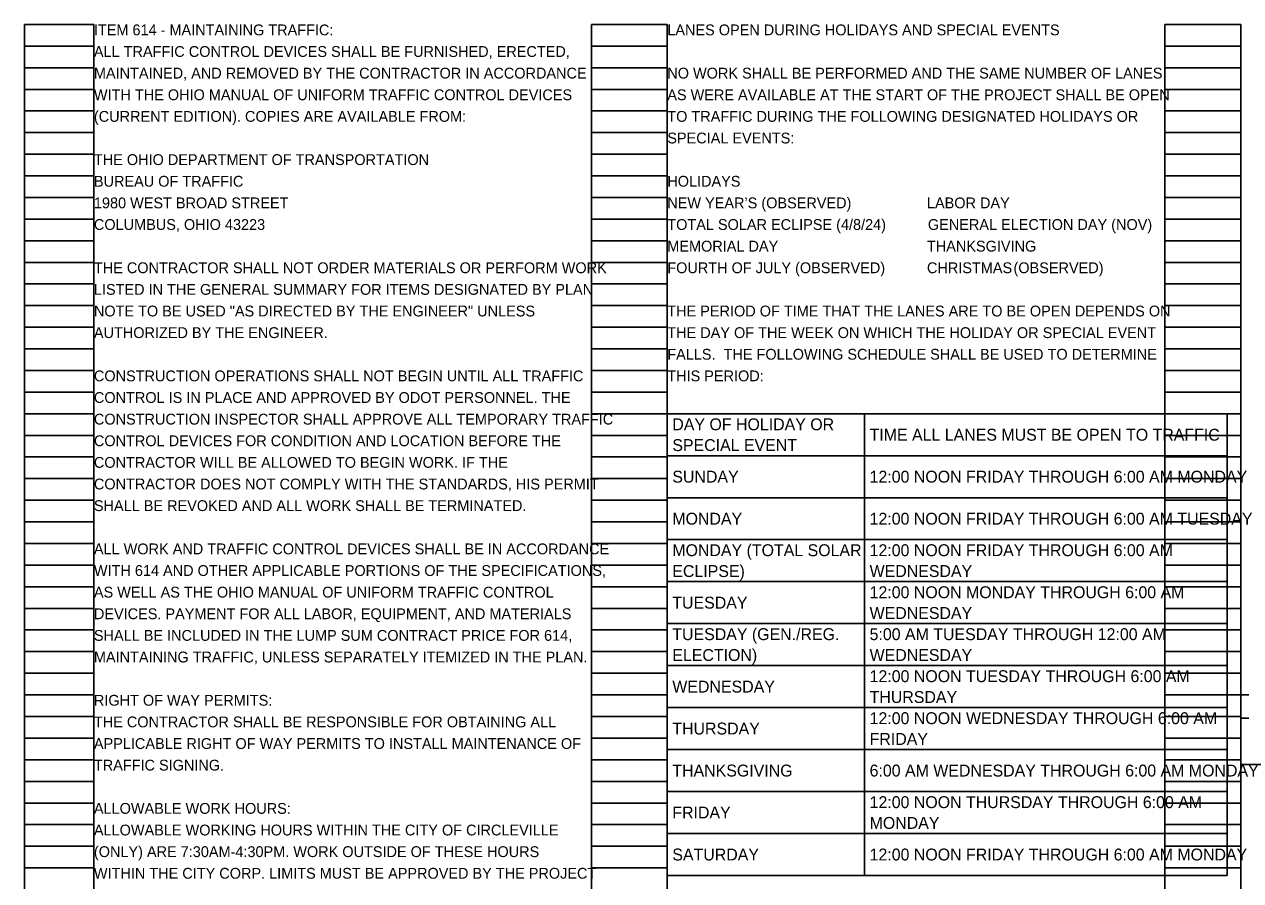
# Model space of a CAD drawing. Extents: x 24172 to 24226.9, y 11011.9 to 11091.2.
# Drawn here: x 24196.45 to 24212.19, y 11080.09 to 11091.18 of the extents above; entities that cross this region are included whole.
import ezdxf

# ---------------------------------------------------------------- set-up
doc = ezdxf.new("R2010")
doc.units = 0
for name, color, linetype in [('SC_Scratch1', 7, 'Continuous'), ('SH_Data', 7, 'Continuous'), ('SH_Text', 7, 'Continuous')]:
    doc.layers.add(name, color=color, linetype=linetype)

msp = doc.modelspace()

# ---------------------------------------------------------------- linework, layer by layer
at = {"layer": 'SH_Data'}
for p, q in [((24196.45, 11071.019), (24196.45, 11091.179)), ((24196.45, 11091.179), (24197.35, 11091.179)), ((24197.35, 11071.019), (24197.35, 11091.179)), ((24203.79, 11071.019), (24203.79, 11091.179)), ((24203.79, 11091.179), (24204.77, 11091.179)), ((24204.77, 11071.019), (24204.77, 11091.179)), ((24211.21, 11071.019), (24211.21, 11091.179)), ((24211.21, 11091.179), (24212.19, 11091.179)), ((24212.19, 11071.019), (24212.19, 11091.179)), ((24196.45, 11090.899), (24197.35, 11090.899)), ((24203.79, 11090.899), (24204.77, 11090.899)), ((24211.21, 11090.899), (24212.19, 11090.899)), ((24196.45, 11090.619), (24197.35, 11090.619)), ((24203.79, 11090.619), (24204.77, 11090.619)), ((24211.21, 11090.619), (24212.19, 11090.619)), ((24196.45, 11090.339), (24197.35, 11090.339)), ((24203.79, 11090.339), (24204.77, 11090.339)), ((24211.21, 11090.339), (24212.19, 11090.339)), ((24196.45, 11090.059), (24197.35, 11090.059)), ((24203.79, 11090.059), (24204.77, 11090.059)), ((24211.21, 11090.059), (24212.19, 11090.059)), ((24196.45, 11089.779), (24197.35, 11089.779)), ((24203.79, 11089.779), (24204.77, 11089.779)), ((24211.21, 11089.779), (24212.19, 11089.779)), ((24196.45, 11089.499), (24197.35, 11089.499)), ((24203.79, 11089.499), (24204.77, 11089.499)), ((24211.21, 11089.499), (24212.19, 11089.499)), ((24196.45, 11089.219), (24197.35, 11089.219)), ((24203.79, 11089.219), (24204.77, 11089.219)), ((24211.21, 11089.219), (24212.19, 11089.219)), ((24196.45, 11088.939), (24197.35, 11088.939)), ((24203.79, 11088.939), (24204.77, 11088.939)), ((24211.21, 11088.939), (24212.19, 11088.939)), ((24196.45, 11088.659), (24197.35, 11088.659)), ((24203.79, 11088.659), (24204.77, 11088.659)), ((24211.21, 11088.659), (24212.19, 11088.659)), ((24196.45, 11088.379), (24197.35, 11088.379)), ((24203.79, 11088.379), (24204.77, 11088.379)), ((24211.21, 11088.379), (24212.19, 11088.379)), ((24196.45, 11088.099), (24197.35, 11088.099)), ((24203.79, 11088.099), (24204.77, 11088.099)), ((24211.21, 11088.099), (24212.19, 11088.099)), ((24196.45, 11087.819), (24197.35, 11087.819)), ((24203.79, 11087.819), (24204.77, 11087.819)), ((24211.21, 11087.819), (24212.19, 11087.819)), ((24196.45, 11087.539), (24197.35, 11087.539)), ((24203.79, 11087.539), (24204.77, 11087.539)), ((24211.21, 11087.539), (24212.19, 11087.539)), ((24196.45, 11087.259), (24197.35, 11087.259)), ((24203.79, 11087.259), (24204.77, 11087.259)), ((24211.21, 11087.259), (24212.19, 11087.259)), ((24196.45, 11086.979), (24197.35, 11086.979)), ((24203.79, 11086.979), (24204.77, 11086.979)), ((24211.21, 11086.979), (24212.19, 11086.979)), ((24196.45, 11086.699), (24197.35, 11086.699)), ((24203.79, 11086.699), (24204.77, 11086.699)), ((24211.21, 11086.699), (24212.19, 11086.699)), ((24196.45, 11086.419), (24197.35, 11086.419)), ((24203.79, 11086.419), (24204.77, 11086.419)), ((24211.21, 11086.419), (24212.19, 11086.419)), ((24196.45, 11086.139), (24197.35, 11086.139)), ((24203.79, 11086.139), (24204.77, 11086.139)), ((24204.77, 11086.139), (24212.017, 11086.139)), ((24204.77, 11086.139), (24204.77, 11080.16)), ((24207.323, 11086.139), (24207.323, 11080.16)), ((24211.21, 11086.139), (24212.19, 11086.139)), ((24212.017, 11086.139), (24212.017, 11080.16)), ((24196.45, 11085.859), (24197.35, 11085.859)), ((24203.79, 11085.859), (24204.77, 11085.859)), ((24211.21, 11085.859), (24212.19, 11085.859)), ((24196.45, 11085.579), (24197.35, 11085.579)), ((24203.79, 11085.579), (24204.77, 11085.579)), ((24204.77, 11085.596), (24212.017, 11085.596)), ((24211.21, 11085.579), (24212.19, 11085.579)), ((24196.45, 11085.299), (24197.35, 11085.299)), ((24203.79, 11085.299), (24204.77, 11085.299)), ((24211.21, 11085.299), (24212.19, 11085.299)), ((24204.77, 11085.052), (24212.017, 11085.052)), ((24196.45, 11085.019), (24197.35, 11085.019)), ((24203.79, 11085.019), (24204.77, 11085.019)), ((24211.21, 11085.019), (24212.19, 11085.019)), ((24196.45, 11084.739), (24197.35, 11084.739)), ((24203.79, 11084.739), (24204.77, 11084.739)), ((24211.21, 11084.739), (24212.19, 11084.739)), ((24196.45, 11084.459), (24197.35, 11084.459)), ((24203.79, 11084.459), (24204.77, 11084.459)), ((24204.77, 11084.509), (24212.017, 11084.509)), ((24211.21, 11084.459), (24212.19, 11084.459)), ((24196.45, 11084.179), (24197.35, 11084.179)), ((24203.79, 11084.179), (24204.77, 11084.179)), ((24211.21, 11084.179), (24212.19, 11084.179)), ((24204.77, 11083.965), (24212.017, 11083.965)), ((24196.45, 11083.899), (24197.35, 11083.899)), ((24203.79, 11083.899), (24204.77, 11083.899)), ((24211.21, 11083.899), (24212.19, 11083.899)), ((24196.45, 11083.619), (24197.35, 11083.619)), ((24203.79, 11083.619), (24204.77, 11083.619)), ((24211.21, 11083.619), (24212.19, 11083.619)), ((24196.45, 11083.339), (24197.35, 11083.339)), ((24203.79, 11083.339), (24204.77, 11083.339)), ((24204.77, 11083.422), (24212.017, 11083.422)), ((24211.21, 11083.339), (24212.19, 11083.339)), ((24196.45, 11083.059), (24197.35, 11083.059)), ((24203.79, 11083.059), (24204.77, 11083.059)), ((24211.21, 11083.059), (24212.19, 11083.059)), ((24204.77, 11082.878), (24212.017, 11082.878)), ((24196.45, 11082.779), (24197.35, 11082.779)), ((24203.79, 11082.779), (24204.77, 11082.779)), ((24211.21, 11082.779), (24212.19, 11082.779)), ((24196.45, 11082.499), (24197.35, 11082.499)), ((24203.79, 11082.499), (24204.77, 11082.499)), ((24211.21, 11082.499), (24212.19, 11082.499)), ((24196.45, 11082.219), (24197.35, 11082.219)), ((24203.79, 11082.219), (24204.77, 11082.219)), ((24204.77, 11082.334), (24212.017, 11082.334)), ((24211.21, 11082.219), (24212.19, 11082.219)), ((24196.45, 11081.939), (24197.35, 11081.939)), ((24203.79, 11081.939), (24204.77, 11081.939)), ((24211.21, 11081.939), (24212.19, 11081.939)), ((24204.77, 11081.791), (24212.017, 11081.791)), ((24196.45, 11081.659), (24197.35, 11081.659)), ((24203.79, 11081.659), (24204.77, 11081.659)), ((24211.21, 11081.659), (24212.19, 11081.659)), ((24196.45, 11081.379), (24197.35, 11081.379)), ((24203.79, 11081.379), (24204.77, 11081.379)), ((24204.77, 11081.247), (24212.017, 11081.247)), ((24211.21, 11081.379), (24212.19, 11081.379)), ((24196.45, 11081.099), (24197.35, 11081.099)), ((24203.79, 11081.099), (24204.77, 11081.099)), ((24211.21, 11081.099), (24212.19, 11081.099)), ((24196.45, 11080.819), (24197.35, 11080.819)), ((24203.79, 11080.819), (24204.77, 11080.819)), ((24211.21, 11080.819), (24212.19, 11080.819)), ((24204.77, 11080.704), (24212.017, 11080.704)), ((24196.45, 11080.539), (24197.35, 11080.539)), ((24203.79, 11080.539), (24204.77, 11080.539)), ((24211.21, 11080.539), (24212.19, 11080.539)), ((24196.45, 11080.259), (24197.35, 11080.259)), ((24203.79, 11080.259), (24204.77, 11080.259)), ((24204.77, 11080.16), (24212.017, 11080.16)), ((24211.21, 11080.259), (24212.19, 11080.259))]:
    msp.add_line(p, q, dxfattribs=at)
at = {"layer": 'SH_Text'}
for p, q in [((24212.19, 11082.499), (24218.58, 11082.499)), ((24212.19, 11082.499), (24212.19, 11077.174)), ((24212.19, 11082.199), (24218.58, 11082.199)), ((24212.19, 11081.599), (24218.58, 11081.599))]:
    msp.add_line(p, q, dxfattribs=at)

# ---------------------------------------------------------------- texts
at = {"layer": 'SC_Scratch1'}
for s, p in [('ITEM 614 - MAINTAINING TRAFFIC:', (24197.35, 11091.039)), ('ALL TRAFFIC CONTROL DEVICES SHALL BE FURNISHED, ERECTED, ', (24197.35, 11090.759)), ('MAINTAINED, AND REMOVED BY THE CONTRACTOR IN ACCORDANCE ', (24197.35, 11090.479)), ('WITH THE OHIO MANUAL OF UNIFORM TRAFFIC CONTROL DEVICES ', (24197.35, 11090.199)), ('(CURRENT EDITION). COPIES ARE AVAILABLE FROM:', (24197.35, 11089.919)), ('THE OHIO DEPARTMENT OF TRANSPORTATION', (24197.35, 11089.359)), ('BUREAU OF TRAFFIC', (24197.35, 11089.079)), ('1980 WEST BROAD STREET', (24197.35, 11088.799)), ('COLUMBUS, OHIO 43223', (24197.35, 11088.519)), ('THE CONTRACTOR SHALL NOT ORDER MATERIALS OR PERFORM WORK ', (24197.35, 11087.959)), ('LISTED IN THE GENERAL SUMMARY FOR ITEMS DESIGNATED BY PLAN ', (24197.35, 11087.679)), ('NOTE TO BE USED "AS DIRECTED BY THE ENGINEER" UNLESS ', (24197.35, 11087.399)), ('AUTHORIZED BY THE ENGINEER.', (24197.35, 11087.119)), ('CONSTRUCTION OPERATIONS SHALL NOT BEGIN UNTIL ALL TRAFFIC ', (24197.35, 11086.559)), ('CONTROL IS IN PLACE AND APPROVED BY ODOT PERSONNEL. THE ', (24197.35, 11086.279)), ('CONSTRUCTION INSPECTOR SHALL APPROVE ALL TEMPORARY TRAFFIC ', (24197.35, 11085.999)), ('CONTROL DEVICES FOR CONDITION AND LOCATION BEFORE THE ', (24197.35, 11085.719)), ('CONTRACTOR WILL BE ALLOWED TO BEGIN WORK. IF THE ', (24197.35, 11085.439)), ('CONTRACTOR DOES NOT COMPLY WITH THE STANDARDS, HIS PERMIT ', (24197.35, 11085.159)), ('SHALL BE REVOKED AND ALL WORK SHALL BE TERMINATED.', (24197.35, 11084.879)), ('ALL WORK AND TRAFFIC CONTROL DEVICES SHALL BE IN ACCORDANCE ', (24197.35, 11084.319)), ('WITH 614 AND OTHER APPLICABLE PORTIONS OF THE SPECIFICATIONS, ', (24197.35, 11084.039)), ('AS WELL AS THE OHIO MANUAL OF UNIFORM TRAFFIC CONTROL ', (24197.35, 11083.759)), ('DEVICES. PAYMENT FOR ALL LABOR, EQUIPMENT, AND MATERIALS ', (24197.35, 11083.479)), ('SHALL BE INCLUDED IN THE LUMP SUM CONTRACT PRICE FOR 614, ', (24197.35, 11083.199)), ('MAINTAINING TRAFFIC, UNLESS SEPARATELY ITEMIZED IN THE PLAN.', (24197.35, 11082.919)), ('RIGHT OF WAY PERMITS:', (24197.35, 11082.359)), ('THE CONTRACTOR SHALL BE RESPONSIBLE FOR OBTAINING ALL ', (24197.35, 11082.079)), ('APPLICABLE RIGHT OF WAY PERMITS TO INSTALL MAINTENANCE OF ', (24197.35, 11081.799)), ('TRAFFIC SIGNING.', (24197.35, 11081.519)), ('ALLOWABLE WORK HOURS:', (24197.35, 11080.959)), ('ALLOWABLE WORKING HOURS WITHIN THE CITY OF CIRCLEVILLE ', (24197.35, 11080.679)), ('(ONLY) ARE 7:30AM-4:30PM. WORK OUTSIDE OF THESE HOURS ', (24197.35, 11080.399)), ('WITHIN THE CITY CORP. LIMITS MUST BE APPROVED BY THE PROJECT ', (24197.35, 11080.119))]:
    msp.add_text(s, height=0.14, dxfattribs=at).set_placement(p)
at = {"layer": 'SH_Data'}
for s, height, p in [('LANES OPEN DURING HOLIDAYS AND SPECIAL EVENTS', 0.14, (24204.77, 11091.039)), ('NO WORK SHALL BE PERFORMED AND THE SAME NUMBER OF LANES ', 0.14, (24204.77, 11090.479)), ('AS WERE AVAILABLE AT THE START OF THE PROJECT SHALL BE OPEN ', 0.14, (24204.77, 11090.199)), ('TO TRAFFIC DURING THE FOLLOWING DESIGNATED HOLIDAYS OR ', 0.14, (24204.77, 11089.919)), ('SPECIAL EVENTS:', 0.14, (24204.77, 11089.639)), ('HOLIDAYS', 0.14, (24204.77, 11089.079)), ('NEW YEAR’S (OBSERVED)', 0.14, (24204.77, 11088.799)), ('LABOR DAY', 0.14, (24208.13, 11088.799)), ('TOTAL SOLAR ECLIPSE (4/8/24)', 0.14, (24204.77, 11088.519)), ('           GENERAL ELECTION DAY (NOV)', 0.14, (24207.57, 11088.519)), ('MEMORIAL DAY ', 0.14, (24204.77, 11088.239)), ('THANKSGIVING', 0.14, (24208.13, 11088.239)), ('FOURTH OF JULY\xa0(OBSERVED)', 0.14, (24204.77, 11087.959)), ('CHRISTMAS', 0.14, (24208.13, 11087.959)), ('(OBSERVED)', 0.14, (24209.25, 11087.959)), ('THE PERIOD OF TIME THAT THE LANES ARE TO BE OPEN DEPENDS ON ', 0.14, (24204.77, 11087.399)), ('THE DAY OF THE WEEK ON WHICH THE HOLIDAY OR SPECIAL EVENT ', 0.14, (24204.77, 11087.119)), ('FALLS.  THE FOLLOWING SCHEDULE SHALL BE USED TO DETERMINE ', 0.14, (24204.77, 11086.839)), ('THIS PERIOD:', 0.14, (24204.77, 11086.559)), ('DAY OF HOLIDAY OR ', 0.154, (24204.835, 11085.925)), ('SPECIAL EVENT', 0.154, (24204.835, 11085.656)), ('TIME ALL LANES MUST BE OPEN TO TRAFFIC', 0.154, (24207.388, 11085.79)), ('SUNDAY', 0.154, (24204.835, 11085.247)), ('12:00 NOON FRIDAY THROUGH 6:00 AM MONDAY', 0.154, (24207.388, 11085.247)), ('MONDAY', 0.154, (24204.835, 11084.703)), ('12:00 NOON FRIDAY THROUGH 6:00 AM TUESDAY', 0.154, (24207.388, 11084.703)), ('MONDAY (TOTAL SOLAR ', 0.154, (24204.835, 11084.295)), ('12:00 NOON FRIDAY THROUGH 6:00 AM ', 0.154, (24207.388, 11084.295)), ('ECLIPSE)', 0.154, (24204.835, 11084.025)), ('WEDNESDAY', 0.154, (24207.388, 11084.025)), ('TUESDAY', 0.154, (24204.835, 11083.616)), ('12:00 NOON MONDAY THROUGH 6:00 AM ', 0.154, (24207.388, 11083.751)), ('WEDNESDAY', 0.154, (24207.388, 11083.482)), ('TUESDAY (GEN./REG. ', 0.154, (24204.835, 11083.208)), ('5:00 AM TUESDAY THROUGH 12:00 AM ', 0.154, (24207.388, 11083.208)), ('ELECTION)', 0.154, (24204.835, 11082.938)), ('WEDNESDAY', 0.154, (24207.388, 11082.938)), ('12:00 NOON TUESDAY THROUGH 6:00 AM ', 0.154, (24207.388, 11082.664)), ('WEDNESDAY', 0.154, (24204.835, 11082.529)), ('THURSDAY', 0.154, (24207.388, 11082.394)), ('12:00 NOON WEDNESDAY THROUGH 6:00 AM ', 0.154, (24207.388, 11082.12)), ('THURSDAY', 0.154, (24204.835, 11081.986)), ('FRIDAY', 0.154, (24207.388, 11081.851)), ('THANKSGIVING', 0.154, (24204.835, 11081.442)), ('6:00 AM WEDNESDAY THROUGH 6:00 AM MONDAY', 0.154, (24207.388, 11081.442)), ('12:00 NOON THURSDAY THROUGH 6:00 AM ', 0.154, (24207.388, 11081.033)), ('FRIDAY', 0.154, (24204.835, 11080.899)), ('MONDAY', 0.154, (24207.388, 11080.764)), ('SATURDAY', 0.154, (24204.835, 11080.355)), ('12:00 NOON FRIDAY THROUGH 6:00 AM MONDAY', 0.154, (24207.388, 11080.355))]:
    msp.add_text(s, height=height, dxfattribs=at).set_placement(p)

doc.saveas('drawing.dxf')
